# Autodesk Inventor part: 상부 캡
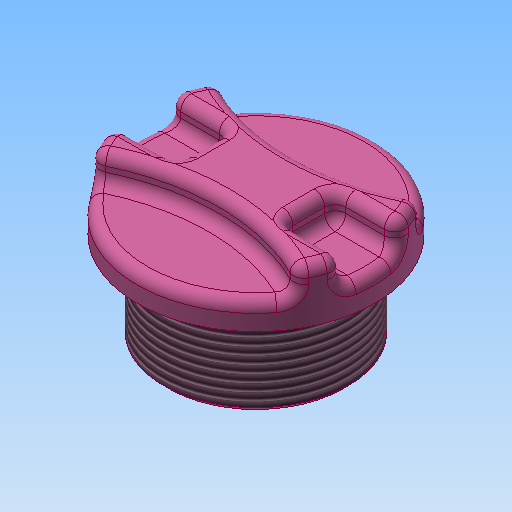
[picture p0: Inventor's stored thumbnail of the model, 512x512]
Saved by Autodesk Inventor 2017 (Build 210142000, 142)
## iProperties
Created: 2016-09
Part Number: 상부 캡
Material: ABS 플라스틱
Document SubType Name: Modeling
Designer: mduedu
Density: 1.06 g/cm^3
Appearance: 분홍색
Author: mduedu
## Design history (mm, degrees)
sketch "스케치1"
  geometry: C1 r 22.5 at (0, 0); 1 further point
  constraints: 1 centre point, 1 coincident
  dimensions: "d0" = 45 diameter of C1
extrude "돌출1" new body sketch "스케치1" distance "d1" = 10; taper "d2" = 0 deg
sketch "스케치2" dims "d4" = 80
  geometry: C1 r 22.5 at (0, 0) reference; 3 further points
  constraints: 3 vertical alignment, 2 other
  dimensions: "d3" = 7 distance of point (0, 7) point (0, 0)
extrude "돌출2" cut sketch "스케치2" distance "d5" = 5; taper "d6" = 0 deg
sketch "스케치3"
  geometry: L1 (-22.5, 0)-(0, 0); L2 (-21.937, 5)-(-10, 5); L3 (-10, 5)-(-10, -5); L4 (-10, -5)-(-21.937, -5); A1 r 22.5 centre (0, 0) between (-19.118, 11.864) and (-19.118, -11.864) reference; A2 r 22.5 centre (0, 0) between (-21.937, 5) and (-21.937, -5); 1 further point
  constraints: 8 end point, 5 point on circle, 2 horizontal, 1 centre point, 1 coincident, 1 parallel, 1 perpendicular, 1 symmetric about line
  dimensions: "d7" = 10 distance from line of L3 point (0, 0); "d8" = 10 distance of L2.end L3.end
extrude "돌출3" cut sketch "스케치3" distance "d9" = 5; taper "d10" = 0 deg
fillet "모깎기1" dims "d11" = 2
fillet "모깎기2" dims "d12" = 2
fillet "모깎기3" dims "d13" = 2
sketch "스케치4"
  geometry: C1 r 17.5 at (0, 0); 1 further point
  constraints: 1 centre point, 1 coincident
  dimensions: "d14" = 35 diameter of C1
extrude "돌출4" join sketch "스케치4" distance "d15" = 17; taper "d16" = 0 deg
sketch "스케치5"
  geometry: C1 r 12.5 at (0, 0); 1 further point
  constraints: 1 centre point, 1 coincident
  dimensions: "d17" = 25 diameter of C1
extrude "돌출5" cut sketch "스케치5" distance "d18" = 10; taper "d19" = 0 deg
fillet "모깎기4" dims "d20" = 3
feature "스레드1" dims "d21" = 10, "d22" = 0
chamfer "모따기1" distance "d23" = 1; stored, may be unused: second distance "d24" = 2, angle "d25" = 45 deg
node "솔리드1"
mirror "대칭1"
mirror "대칭2"
node "투영된 루프1"
